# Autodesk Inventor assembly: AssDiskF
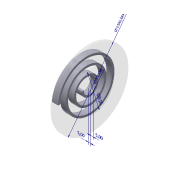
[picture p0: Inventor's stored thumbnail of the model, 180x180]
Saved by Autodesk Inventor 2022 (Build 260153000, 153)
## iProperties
Created: 2013-08
Part Number: AssDiskF
Document SubType Name: Assembly
Designer: hunter love
Mass: 142.998 g
Surface Area: 599.909 cm^2
Volume: 142.998 cm^3
Density: 1 g/cm^3
Author: hunter love
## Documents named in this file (3)
- C:\Users\x300\Desktop\compressore scroll\AssDiskF.iam
- C:\Users\x300\Desktop\compressore scroll\WheelFBase.ipt
- C:\Users\x300\Desktop\compressore scroll\WheelFGear.ipt
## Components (2 placed, 2 different names)
1. WheelFBase:1 — Mate:1, Mate:2, Mate:3, Coincidente:4
2. WheelFGear:1 — Mate:1, Mate:2, Mate:3
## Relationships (4: Mate 4)
- Mate:1: WheelFBase:1 ↔ WheelFGear:1
- Mate:2: WheelFBase:1 ↔ WheelFGear:1
- Mate:3: WheelFBase:1 ↔ WheelFGear:1
- Coincidente:4 [Mate]: WheelFBase:1
